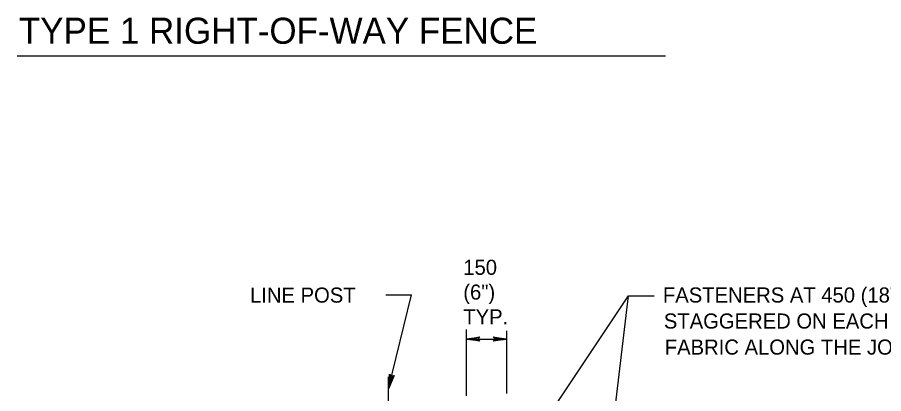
# Model space of a CAD drawing. Extents: x 13 to 918, y -903 to 879.
# Drawn here: x 295.7 to 474.8, y -116.4 to -38.5 of the extents above; entities that cross this region are included whole.
import ezdxf

# ---------------------------------------------------------------- set-up
doc = ezdxf.new("R2010")
doc.units = 0
for name, color, linetype in [('1', 7, 'Continuous'), ('2', 7, 'Continuous'), ('3', 7, 'Continuous')]:
    doc.layers.add(name, color=color, linetype=linetype)

msp = doc.modelspace()

# ---------------------------------------------------------------- linework, layer by layer
at = {"layer": '2'}
for p, q in [((371.8315, -95.985), (377.1315, -95.985)), ((422.0315, -96.158), (427.3315, -96.158)), ((388.521, -116.82675), (388.521, -103.15175)), ((396.85425, -116.385), (396.85425, -103.38075)), ((388.521, -105.0955), (396.85425, -105.0955)), ((372.32525, -112.8975), (372.32525, -240.62675))]:
    msp.add_line(p, q, dxfattribs=at)
at = {"layer": '3'}
for p, q in [((295.69151, -46.51975), (429.66356, -46.51975)), ((372.38775, -115.408), (377.1315, -95.985)), ((381.11475, -157.41625), (422.0315, -96.158)), ((413.5335, -167.35175), (422.0315, -96.158))]:
    msp.add_line(p, q, dxfattribs=at)
for points in [[(391.169, -105.42875), (391.071, -105.237), (388.521, -105.0955), (391.169, -105.42875), (391.3065, -105.54325), (388.521, -105.0955), (391.069, -104.9705), (391.16275, -104.77875), (388.521, -105.0955), (391.3065, -104.65375), (391.16275, -104.77875)], [(394.2065, -104.762), (394.30425, -104.95375), (396.85425, -105.0955), (394.2065, -104.762), (394.069, -104.6475), (396.85425, -105.0955), (394.3065, -105.2205), (394.21275, -105.412), (396.85425, -105.0955), (394.069, -105.537), (394.21275, -105.412)], [(373.4065, -112.735), (373.1815, -112.78925), (372.38775, -115.408), (373.4065, -112.735), (373.56275, -112.6245), (372.38775, -115.408), (372.90425, -112.7245), (372.7315, -112.57875), (372.38775, -115.408), (372.6355, -112.3975), (372.7315, -112.57875)]]:
    msp.add_lwpolyline(points, dxfattribs=at)

# ---------------------------------------------------------------- texts
at = {"layer": '1'}
for s, p in [('150', (387.86675, -91.818)), ('(6")', (387.86675, -96.943)), ('TYP.', (387.86675, -102.068))]:
    msp.add_text(s, height=3.124999, dxfattribs=at).set_placement(p)
at = {"layer": '3'}
for s, height, p in [('TYPE 1 RIGHT-OF-WAY FENCE', 5.4020865, (296.01425, -43.99475)), ('LINE POST', 3.124999, (343.78775, -97.56825)), ('FASTENERS AT 450 (18") C TO C AND', 3.1249995, (429.12725, -97.5495)), ('STAGGERED ON EACH EDGE OF', 3.1249995, (429.319, -102.93925)), ('FABRIC ALONG THE JOINT', 3.1249995, (429.51275, -108.33075))]:
    msp.add_text(s, height=height, dxfattribs=at).set_placement(p)

doc.saveas('drawing.dxf')
